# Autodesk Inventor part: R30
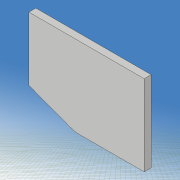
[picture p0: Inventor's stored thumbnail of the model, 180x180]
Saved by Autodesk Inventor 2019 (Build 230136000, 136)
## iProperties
Created: 2021-05
Part Number: R30
Material: 一般
Document SubType Name: Modeling
Designer: kikut
Density: 1 g/cm^3
Appearance: 既定
Mass: 0.0360182 g
Surface Area: 1.42664 cm^2
Volume: 0.0360182 cm^3
Author: kikut
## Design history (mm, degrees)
sketch "スケッチ1"
  geometry: L1 (80, 60)-(-80, 60); L2 (-80, 60)-(-80, -60); L3 (-80, -60)-(80, -60); L4 (80, -60)-(80, 60); L5 (80, 60)-(-80, -60); L6 (-80, 60)-(80, -60); 1 further point
  constraints: 12 end point, 2 midpoint, 2 parallel, 1 horizontal, 1 perpendicular
  dimensions: "d0" = 160 distance of L2.end L3.end; "d1" = 120 distance of L1.end L2.end
extrude "押し出し1" new body sketch "スケッチ1" stored distance "d2" = 0.6; taper "d3" = 0 deg
sketch "スケッチ2"
  geometry: L1 (-140, 0)-(140, 0) reference; L2 (0, -54)-(20, -30); L3 (0, 54)-(20, 30); L4 (0, -3)-(6.514, -3); L5 (6.514, -3)-(16, -6); L6 (16, -6)-(24, -3); L7 (24, -3)-(33.716, -3); L8 (0, 3)-(6.514, 3); L9 (6.514, 3)-(16, 6); L10 (16, 6)-(24, 3); L11 (24, 3)-(33.716, 3); L12 (0, -98)-(0, 98) reference; L13 (-100, -70)-(100, -70); L14 (100, -70)-(100, 70); L15 (100, 70)-(-100, 70); L16 (-100, 70)-(-100, -70); L17 (-100, -70)-(100, 70); L18 (100, -70)-(-100, 70); A1 r 60 centre (54.312, 28.5) between (0, 54) and (0, 3); A2 r 60 centre (54.312, -28.5) between (0, -3) and (0, -54); A3 r 18.111 centre (18, -12) between (20, -30) and (33.716, -3); A4 r 18.111 centre (18, 12) between (33.716, 3) and (20, 30); 1 further point
  constraints: 32 end point, 8 point on circle, 8 symmetric about line, 4 centre point, 3 horizontal, 2 collinear, 2 midpoint, 2 parallel, 1 perpendicular
  dimensions: "d5" = 60 radius of A1; "d6" = 6 distance of L8.start L4.start; "d7" = 108 distance of L3.start L2.start; "d8" = 0 horizontal distance of L3.start L8.start; "d9" = 60 distance of L3.end L2.end; "d10" = 0 horizontal distance of point (0, 0) L3.start; "d11" = 20 horizontal distance of L3.start L3.end; "d12" = 24 distance of A4.centre A3.centre; "d13" = 6 distance of L11.end L7.end; "d14" = 12 distance of L9.end L5.end; "d15" = 16 distance from line of L12 L5.end; "d16" = 24 distance from line of L6.end L12; "d17" = 200 distance of L14.end L15.end; "d18" = 140 distance of L15.end L13.start; "d30" = 18 distance from line of L12 A4.centre
extrude "押し出し2" cut sketch "スケッチ2" stored distance "d19" = 10; taper "d20" = 0 deg
sketch "スケッチ3"
  geometry: L1 (49.705, -17.97)-(33.948, -15.191); L2 (33.948, -15.191)-(34.295, -13.222); L3 (34.295, -13.222)-(50.052, -16); L4 (50.052, -16)-(49.705, -17.97); L5 (49.705, -17.97)-(34.295, -13.222); L6 (33.948, -15.191)-(50.052, -16); L7 (50.052, 16)-(34.295, 13.222); L8 (34.295, 13.222)-(33.948, 15.191); L9 (33.948, 15.191)-(49.705, 17.97); L10 (49.705, 17.97)-(50.052, 16); L11 (50.052, 16)-(33.948, 15.191); L12 (34.295, 13.222)-(49.705, 17.97); L13 (-112, 0)-(112, 0) reference; L14 (0, -84)-(0, 84) reference; 3 further points
  constraints: 24 end point, 4 midpoint, 4 parallel, 2 perpendicular, 2 symmetric about line
  dimensions: "d21" = 2 distance of L3.end L1.start; "d22" = 2 distance of L9.end L7.start; "d23" = 16 distance of L8.end L9.end; "d24" = 42 distance from line of L14 point (42, 15.596); "d26" = 10 deg angle of L7 L13; "d62" = 16 distance from line of L3.end L13
extrude "押し出し3" join sketch "スケッチ3" distance "d27" = 0.6; taper "d28" = 0 deg
fillet "フィレット1" dims "d31" = 2
fillet "フィレット2" dims "d32" = 1
sketch "スケッチ6"
  geometry: L1 (-20, 60)-(80, 60); L2 (80, 60)-(80, -60); L3 (80, -60)-(-20, -60); L4 (-20, -60)-(-20, 60); L5 (-46.168, 0)-(93.832, 0) reference; L6 (0, -84)-(0, 84) reference; L7 (20, 0)-(30, 0); L8 (30, 0)-(30, 10); L9 (30, 10)-(20, 10); L10 (20, 10)-(20, 0); 1 further point
  constraints: 16 end point, 4 parallel, 2 horizontal, 2 perpendicular, 1 other
  dimensions: "d63" = 120 distance of L3.end L1.start; "d64" = 100 distance of L1.start L1.end; "d65" = 20 distance between parallel lines of L6 L4; "d66" = 10 distance of L8.end L9.end; "d73" = 10 distance of L9.end L7.start; "d74" = 0 distance between parallel lines of L7 L5; "d75" = 40 distance between parallel lines of L10 L4
extrude "押し出し4" cut sketch "スケッチ6" stored distance "d70" = 10; taper "d71" = 0 deg
node "ソリッド1"
